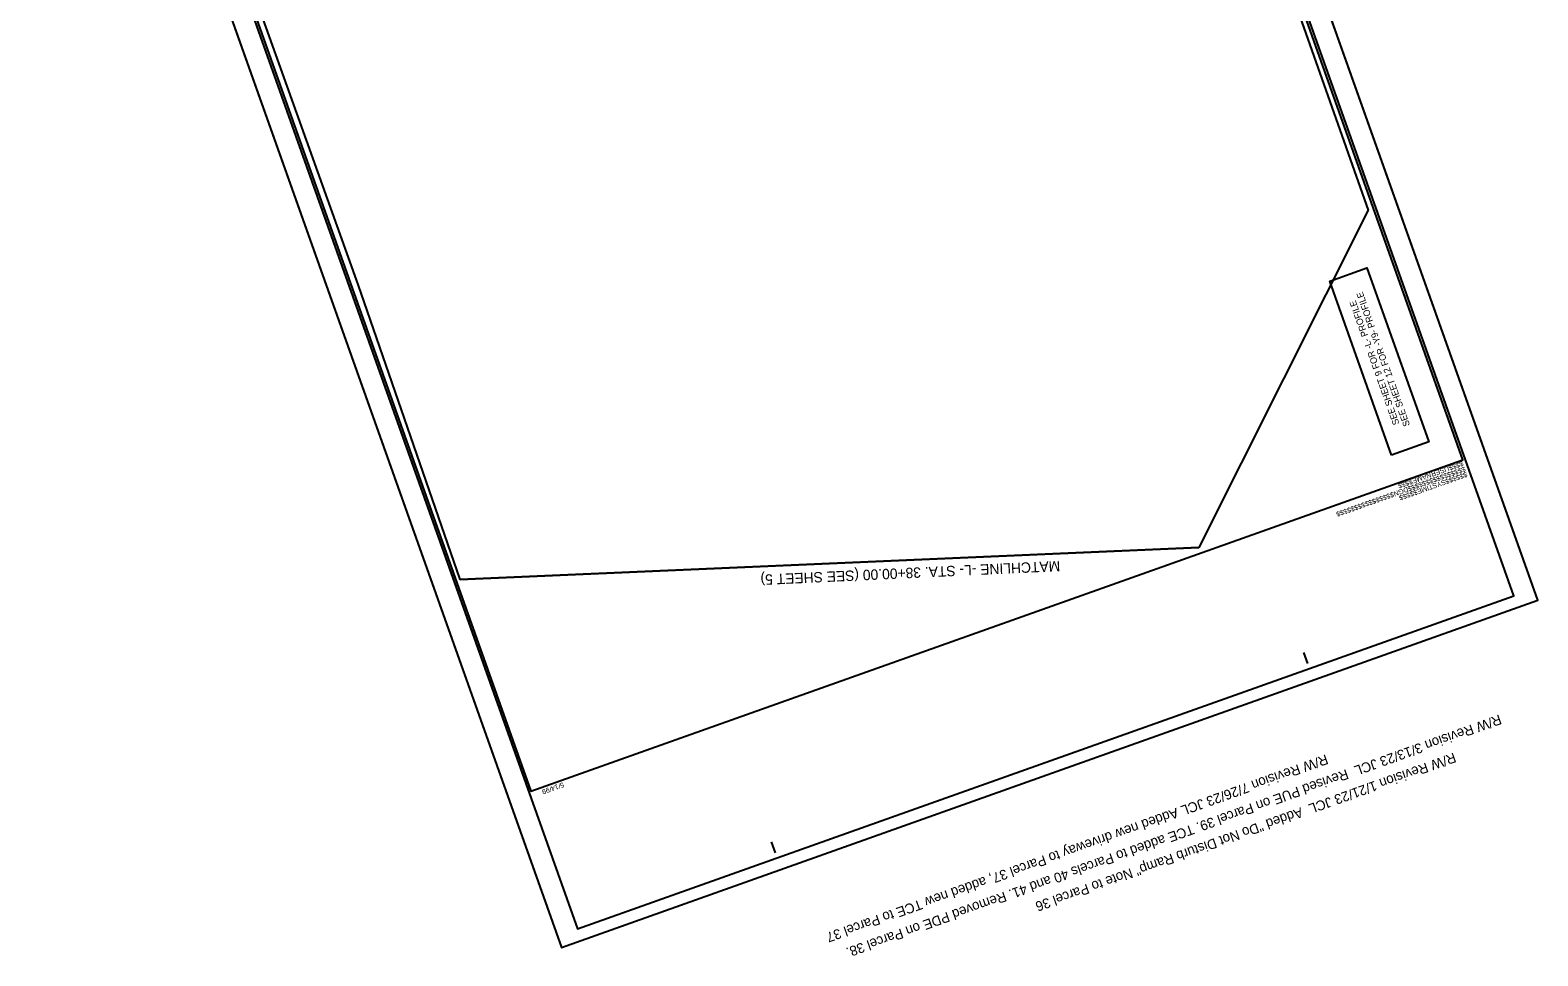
# Model space of a CAD drawing. Extents: x 1615843 to 1617444, y 901957 to 903921.
# Drawn here: x 1615843 to 1617444, y 901957 to 902939 of the extents above; entities that cross this region are included whole.
import ezdxf

# ---------------------------------------------------------------- set-up
doc = ezdxf.new("R2010")
doc.units = 0
for name, color, linetype in [('Exist Plan Preparation Drainage Flow Arrows', 7, 'Continuous'), ('Exist Plan Preparation Drainage Notes Label', 7, 'Continuous'), ('Exist Structure Minor Pipes CMP 24 Inch Text', 7, 'Continuous'), ('Exist Structure Minor Pipes RCP 12 Inch', 7, 'Continuous'), ('Exist Structure Minor Pipes RCP 15 Inch Text', 7, 'Continuous'), ('Exist Structure Minor Pipes RCP 24 Inch Text', 7, 'Continuous'), ('Prop Drainage Structure Plot Symbol 50 Scale', 7, 'Continuous'), ('Prop Plan Preparation Cover Label', 7, 'Continuous'), ('Prop Plan Preparation Crest Label', 7, 'Continuous')]:
    doc.layers.add(name, color=color, linetype=linetype)

msp = doc.modelspace()

# ---------------------------------------------------------------- linework, layer by layer
at = {"layer": 'Exist Plan Preparation Drainage Flow Arrows'}
msp.add_lwpolyline([(1615865.7, 903555.7), (1616423.9, 901985.4), (1617418.1, 902338.9), (1616859.8, 903909.1)], close=True, dxfattribs=at)
at = {"layer": 'Exist Plan Preparation Drainage Notes Label'}
msp.add_lwpolyline([(1615843, 903552.4), (1616407.1, 901965.7), (1617443.6, 902334.1), (1616879.5, 903920.8)], close=True, dxfattribs=at)
at = {"layer": 'Exist Structure Minor Pipes CMP 24 Inch Text'}
for p, q in [((1617443.6, 902334.1), (1616879.5, 903920.8)), ((1615843, 903552.4), (1616407.1, 901965.7)), ((1616407.1, 901965.7), (1617443.6, 902334.1))]:
    msp.add_line(p, q, dxfattribs=at)
at = {"layer": 'Exist Structure Minor Pipes RCP 15 Inch Text'}
msp.add_lwpolyline([(1617288.2, 902488.1), (1617222.6, 902672.6), (1617262.1, 902686.7), (1617327.7, 902502.1)], close=True, dxfattribs=at)
at = {"layer": 'Exist Structure Minor Pipes RCP 24 Inch Text'}
msp.add_line((1616299.5, 902356.1), (1617083.5, 902390), dxfattribs=at)
at = {"layer": 'Prop Plan Preparation Cover Label'}
for p, q in [((1617199.5, 902267), (1617195.3, 902278.8)), ((1616374.4, 902132.3), (1616374.4, 902132.3)), ((1616634.1, 902066), (1616629.9, 902077.8))]:
    msp.add_line(p, q, dxfattribs=at)
msp.add_lwpolyline([(1615872.3, 903544.7), (1616374.7, 902131.4), (1617364.1, 902483.1), (1616861.6, 903896.5)], close=True, dxfattribs=at)
at = {"layer": 'Prop Plan Preparation Crest Label'}
msp.add_lwpolyline([(1616920.6, 902383), (1616299.5, 902356.1), (1616191.2, 902669.1), (1615953.1, 903334.3), (1616369.2, 903520.6), (1616903.3, 903759.8), (1617120.2, 903154.3), (1617263.4, 902747.8), (1617083.5, 902390)], close=True, dxfattribs=at)

# ---------------------------------------------------------------- texts
at = {"layer": 'Exist Structure Minor Pipes RCP 12 Inch'}
msp.add_text('MATCHLINE -L- STA. 38+00.00 (SEE SHEET 5)', height=11, rotation=182.6625, dxfattribs=at).set_placement((1616936.2, 902376))
at = {"layer": 'Exist Structure Minor Pipes RCP 15 Inch Text'}
for s, p in [('SEE SHEET 12 FOR -Y9- PROFILE', (1617307.9, 902519.9)), ('SEE SHEET 9 FOR -L- PROFILE', (1617296.7, 902521.5))]:
    msp.add_text(s, height=7, rotation=109.5707, dxfattribs=at).set_placement(p)
at = {"layer": 'Prop Drainage Structure Plot Symbol 50 Scale'}
for s, p in [('R/W Revision 3/13/23 JCL  Revised PUE on Parcel 39. TCE added to Parcels 40 and 41. Removed PDE on Parcel 38.', (1617402.6, 902213.1)), ('R/W Revision 7/26/23 JCL Added new driveway to Parcel 37, added new TCE to Parcel 37', (1617218.5, 902170.8)), ('R/W Revision 1/21/23 JCL  Added "Do Not Disturb Ramp" Note to Parcel 36', (1617354.3, 902172.7))]:
    msp.add_text(s, height=10.5, rotation=199.6756, dxfattribs=at).set_placement(p)
at = {"layer": 'Prop Plan Preparation Cover Label'}
for s, p in [('$$$$USERNAME$$$$', (1617363.5, 902482)), ('$$$$$$$$$$$$$$$$DGN$$$$$$$$$$$$$$$$', (1617365.7, 902476.1)), ('$$$$$$SYSTIME$$$$$', (1617367.5, 902470.3)), ('5/14/99', (1616408.6, 902141.1))]:
    msp.add_text(s, height=5.25, rotation=199.5707, dxfattribs=at).set_placement(p)

doc.saveas('drawing.dxf')
